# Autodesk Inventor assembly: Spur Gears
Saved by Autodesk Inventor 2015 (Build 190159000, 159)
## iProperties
Created: 2014-08
Part Number: Spur Gears
Document SubType Name: Assembly
Designer: User
Categories: <?xml version="1.0" encoding="UTF-16"?> <MemberInstance><Categories><FamilyTemplate/><ParamToTemplateMap><ParamToTemplate><ParamToTemplate CategoryParameter="//
ClientObjectVersion: 1
Author: User
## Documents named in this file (3)
- Z:\CAD Files\Gears\Internal_Helical_Gear_Assembly\Design Accelerator\Spur Gears1.iam
- Z:\CAD Files\Gears\Internal_Helical_Gear_Assembly\Design Accelerator\Spur Gear21.ipt
- Z:\CAD Files\Gears\Internal_Helical_Gear_Assembly\Design Accelerator\Spur Gear12.ipt
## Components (2 placed, 2 different names)
1. Spur Gear2:1 — Rotation:1
2. Spur Gear1:1 — Rotation:1
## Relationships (1: RelateRotation 1)
- Rotation:1 [RelateRotation]: Spur Gear2:1 ↔ Spur Gear1:1
